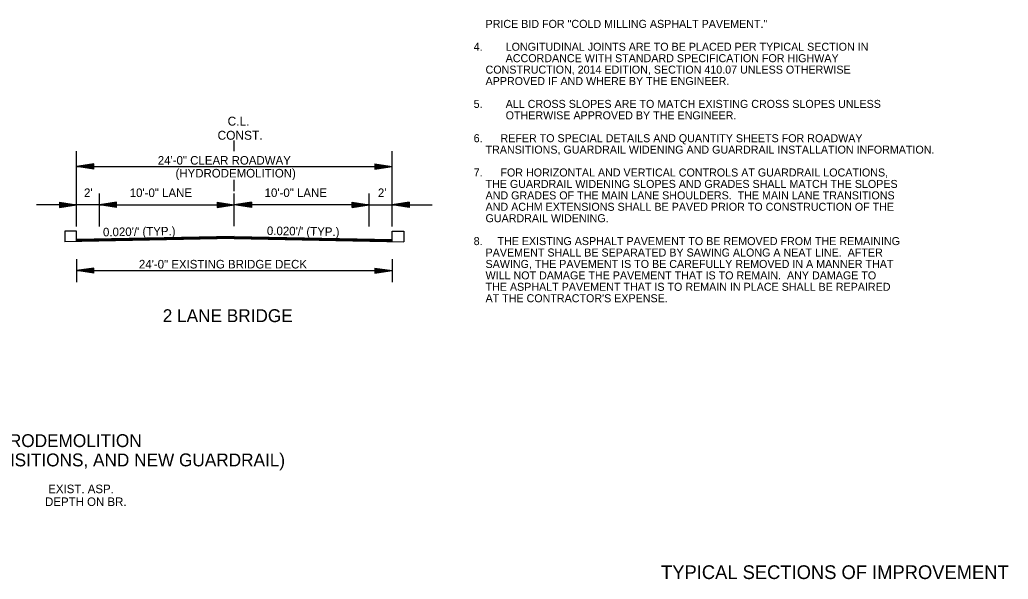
# Model space of a CAD drawing. Extents: x 544259 to 1930787, y -1961343 to 596640.
# Drawn here: x 544903 to 545768, y -1961343 to -1960854 of the extents above; entities that cross this region are included whole.
import ezdxf

# ---------------------------------------------------------------- set-up
doc = ezdxf.new("R2010")
doc.units = 0
for name, color, linetype in [('R_Border', 7, 'Continuous'), ('R_Border Notes', 7, 'Continuous'), ('R_Draft', 7, 'Continuous')]:
    doc.layers.add(name, color=color, linetype=linetype)

msp = doc.modelspace()

# ---------------------------------------------------------------- linework, layer by layer
at = {"layer": 'R_Border'}
for p, q in [((544952.87, -1961015.49), (544917.87, -1961015.49)), ((545228.87, -1961015.49), (545263.87, -1961015.49)), ((544942.71, -1961038.56), (544942.69, -1961047.73)), ((544952.87, -1961038.56), (544942.71, -1961038.56)), ((544952.87, -1961047.36), (544952.87, -1961038.56)), ((545228.87, -1961047.36), (545228.87, -1961038.56)), ((545228.87, -1961038.56), (545239.04, -1961038.56)), ((545239.04, -1961038.56), (545239.05, -1961047.73))]:
    msp.add_line(p, q, dxfattribs=at)
at = {"layer": 'R_Draft'}
for p, q in [((545090.87, -1960968.54), (545090.87, -1960959.24)), ((544952.87, -1961034.32), (544952.87, -1960968.59)), ((545228.87, -1961034.32), (545228.87, -1960968.59)), ((544967.87, -1960979.7), (544952.87, -1960981.95)), ((544967.87, -1960980.08), (544955.38, -1960981.95)), ((544967.87, -1960980.46), (544957.96, -1960981.95)), ((544967.87, -1960980.84), (544960.46, -1960981.95)), ((544967.87, -1960984.2), (544967.87, -1960979.7)), ((545213.87, -1960979.7), (545228.87, -1960981.95)), ((545213.87, -1960979.7), (545213.87, -1960984.2)), ((545213.87, -1960980.08), (545226.37, -1960981.95)), ((545213.87, -1960980.46), (545223.79, -1960981.95)), ((545213.87, -1960980.84), (545221.29, -1960981.95)), ((544952.87, -1960981.95), (545228.87, -1960981.95)), ((544967.87, -1960984.2), (544952.87, -1960981.95)), ((544967.87, -1960983.83), (544955.38, -1960981.95)), ((544967.87, -1960983.45), (544957.96, -1960981.95)), ((544967.87, -1960983.07), (544960.46, -1960981.95)), ((544967.87, -1960981.22), (544963, -1960981.95)), ((544967.87, -1960982.68), (544963, -1960981.95)), ((544967.87, -1960981.6), (544965.5, -1960981.95)), ((544967.87, -1960982.31), (544965.5, -1960981.95)), ((545213.87, -1960981.23), (545218.75, -1960981.95)), ((545213.87, -1960981.6), (545216.24, -1960981.95)), ((545213.87, -1960984.2), (545228.87, -1960981.95)), ((545213.87, -1960982.69), (545218.75, -1960981.95)), ((545213.87, -1960983.45), (545223.79, -1960981.95)), ((545213.87, -1960983.83), (545226.37, -1960981.95)), ((545213.87, -1960983.07), (545221.29, -1960981.95)), ((545213.87, -1960982.31), (545216.24, -1960981.95)), ((545090.87, -1961003.48), (545090.87, -1960993.61)), ((544972.87, -1961034.32), (544972.87, -1961005.6)), ((545090.87, -1961034.15), (545090.87, -1961005.6)), ((545208.87, -1961034.32), (545208.87, -1961005.6)), ((544937.87, -1961013.24), (544952.87, -1961015.49)), ((544937.87, -1961013.24), (544937.87, -1961017.74)), ((544937.87, -1961013.62), (544950.37, -1961015.49)), ((544937.87, -1961014), (544947.79, -1961015.49)), ((544937.87, -1961014.37), (544945.29, -1961015.49)), ((544937.87, -1961014.76), (544942.75, -1961015.49)), ((544937.87, -1961015.14), (544940.24, -1961015.49)), ((544937.87, -1961017.74), (544952.87, -1961015.49)), ((544937.87, -1961016.23), (544942.75, -1961015.49)), ((544937.87, -1961016.98), (544947.79, -1961015.49)), ((544937.87, -1961017.37), (544950.37, -1961015.49)), ((544937.87, -1961016.61), (544945.29, -1961015.49)), ((544937.87, -1961015.84), (544940.24, -1961015.49)), ((544972.87, -1961015.49), (544947.87, -1961015.49)), ((544987.87, -1961013.24), (544972.87, -1961015.49)), ((544987.87, -1961017.74), (544972.87, -1961015.49)), ((544972.87, -1961015.49), (545090.87, -1961015.49)), ((544987.87, -1961013.62), (544975.38, -1961015.49)), ((544987.87, -1961017.37), (544975.38, -1961015.49)), ((544987.87, -1961014), (544977.96, -1961015.49)), ((544987.87, -1961016.98), (544977.96, -1961015.49)), ((544987.87, -1961014.37), (544980.46, -1961015.49)), ((544987.87, -1961016.61), (544980.46, -1961015.49)), ((544987.87, -1961014.76), (544983, -1961015.49)), ((544987.87, -1961016.22), (544983, -1961015.49)), ((544987.87, -1961015.14), (544985.5, -1961015.49)), ((544987.87, -1961015.84), (544985.5, -1961015.49)), ((544987.87, -1961017.74), (544987.87, -1961013.24)), ((545075.87, -1961013.24), (545090.87, -1961015.49)), ((545075.87, -1961013.24), (545075.87, -1961017.74)), ((545075.87, -1961013.62), (545088.37, -1961015.49)), ((545075.87, -1961014), (545085.79, -1961015.49)), ((545075.87, -1961014.37), (545083.29, -1961015.49)), ((545075.87, -1961014.76), (545080.75, -1961015.49)), ((545075.87, -1961015.14), (545078.24, -1961015.49)), ((545075.87, -1961017.74), (545090.87, -1961015.49)), ((545075.87, -1961016.23), (545080.75, -1961015.49)), ((545075.87, -1961016.98), (545085.79, -1961015.49)), ((545075.87, -1961017.37), (545088.37, -1961015.49)), ((545075.87, -1961016.61), (545083.29, -1961015.49)), ((545075.87, -1961015.84), (545078.24, -1961015.49)), ((545105.87, -1961013.24), (545090.87, -1961015.49)), ((545208.87, -1961015.49), (545090.87, -1961015.49)), ((545105.87, -1961017.74), (545090.87, -1961015.49)), ((545105.87, -1961013.62), (545093.38, -1961015.49)), ((545105.87, -1961017.37), (545093.38, -1961015.49)), ((545105.87, -1961014), (545095.96, -1961015.49)), ((545105.87, -1961016.98), (545095.96, -1961015.49)), ((545105.87, -1961014.37), (545098.46, -1961015.49)), ((545105.87, -1961016.61), (545098.46, -1961015.49)), ((545105.87, -1961014.76), (545101, -1961015.49)), ((545105.87, -1961016.23), (545101, -1961015.49)), ((545105.87, -1961015.14), (545103.5, -1961015.49)), ((545105.87, -1961015.84), (545103.5, -1961015.49)), ((545105.87, -1961013.24), (545105.87, -1961017.74)), ((545193.87, -1961013.24), (545208.87, -1961015.49)), ((545193.87, -1961017.74), (545193.87, -1961013.24)), ((545193.87, -1961013.62), (545206.37, -1961015.49)), ((545193.87, -1961014), (545203.79, -1961015.49)), ((545193.87, -1961014.37), (545201.29, -1961015.49)), ((545193.87, -1961014.76), (545198.75, -1961015.49)), ((545193.87, -1961015.14), (545196.24, -1961015.49)), ((545193.87, -1961017.74), (545208.87, -1961015.49)), ((545193.87, -1961016.22), (545198.75, -1961015.49)), ((545193.87, -1961016.98), (545203.79, -1961015.49)), ((545193.87, -1961017.37), (545206.37, -1961015.49)), ((545193.87, -1961016.61), (545201.29, -1961015.49)), ((545193.87, -1961015.84), (545196.24, -1961015.49)), ((545208.87, -1961015.49), (545228.87, -1961015.49)), ((545243.87, -1961013.24), (545228.87, -1961015.49)), ((545243.87, -1961017.74), (545228.87, -1961015.49)), ((545243.87, -1961013.62), (545231.38, -1961015.49)), ((545243.87, -1961017.37), (545231.38, -1961015.49)), ((545243.87, -1961014), (545233.96, -1961015.49)), ((545243.87, -1961016.98), (545233.96, -1961015.49)), ((545243.87, -1961014.37), (545236.46, -1961015.49)), ((545243.87, -1961016.61), (545236.46, -1961015.49)), ((545243.87, -1961014.76), (545239, -1961015.49)), ((545243.87, -1961016.23), (545239, -1961015.49)), ((545243.87, -1961015.14), (545241.5, -1961015.49)), ((545243.87, -1961015.84), (545241.5, -1961015.49)), ((545243.87, -1961013.24), (545243.87, -1961017.74)), ((545090.91, -1961044.77), (544942.69, -1961047.73)), ((545090.87, -1961043.1), (544952.87, -1961045.86)), ((545090.88, -1961043.4), (544952.87, -1961046.16)), ((545090.89, -1961043.7), (544952.87, -1961046.46)), ((545090.89, -1961044), (544952.87, -1961046.76)), ((545090.9, -1961044.3), (544952.87, -1961047.06)), ((545090.9, -1961044.6), (544952.87, -1961047.36)), ((545090.84, -1961044.6), (545228.87, -1961047.36)), ((545090.84, -1961044.77), (545239.05, -1961047.73)), ((545090.85, -1961044.3), (545228.87, -1961047.06)), ((545090.86, -1961043.7), (545228.87, -1961046.46)), ((545090.86, -1961044), (545228.87, -1961046.76)), ((545090.87, -1961043.1), (545228.87, -1961045.86)), ((545090.87, -1961043.4), (545228.87, -1961046.16)), ((544952.87, -1961062.96), (544952.87, -1961082.96)), ((545228.87, -1961062.96), (545228.87, -1961082.96)), ((544967.87, -1961070.71), (544952.87, -1961072.96)), ((544952.87, -1961072.96), (545228.87, -1961072.96)), ((544967.87, -1961075.21), (544952.87, -1961072.96)), ((544967.87, -1961071.08), (544955.38, -1961072.96)), ((544967.87, -1961074.83), (544955.38, -1961072.96)), ((544967.87, -1961071.46), (544957.96, -1961072.96)), ((544967.87, -1961074.45), (544957.96, -1961072.96)), ((544967.87, -1961071.84), (544960.46, -1961072.96)), ((544967.87, -1961074.07), (544960.46, -1961072.96)), ((544967.87, -1961072.22), (544963, -1961072.96)), ((544967.87, -1961073.68), (544963, -1961072.96)), ((544967.87, -1961072.6), (544965.5, -1961072.96)), ((544967.87, -1961073.31), (544965.5, -1961072.96)), ((544967.87, -1961075.21), (544967.87, -1961070.71)), ((545213.87, -1961070.71), (545228.87, -1961072.96)), ((545213.87, -1961070.71), (545213.87, -1961075.21)), ((545213.87, -1961071.08), (545226.37, -1961072.96)), ((545213.87, -1961071.46), (545223.79, -1961072.96)), ((545213.87, -1961071.84), (545221.29, -1961072.96)), ((545213.87, -1961072.23), (545218.75, -1961072.96)), ((545213.87, -1961072.6), (545216.24, -1961072.96)), ((545213.87, -1961075.21), (545228.87, -1961072.96)), ((545213.87, -1961073.69), (545218.75, -1961072.96)), ((545213.87, -1961074.45), (545223.79, -1961072.96)), ((545213.87, -1961074.83), (545226.37, -1961072.96)), ((545213.87, -1961074.07), (545221.29, -1961072.96)), ((545213.87, -1961073.31), (545216.24, -1961072.96))]:
    msp.add_line(p, q, dxfattribs=at)

# ---------------------------------------------------------------- texts
at = {"layer": 'R_Border'}
msp.add_text('TYPICAL SECTIONS OF IMPROVEMENT', height=12, rotation=360, dxfattribs=at).set_placement((545464.19, -1961342.8))
at = {"layer": 'R_Border Notes'}
for s, p in [('    PRICE BID FOR "COLD MILLING ASPHALT PAVEMENT."', (545300.26, -1960860.66)), ('4.', (545300.26, -1960880.66)), ('LONGITUDINAL JOINTS ARE TO BE PLACED PER TYPICAL SECTION IN ', (545328.26, -1960880.66)), ('ACCORDANCE WITH STANDARD SPECIFICATION FOR HIGHWAY', (545328.26, -1960890.66)), ('    CONSTRUCTION, 2014 EDITION, SECTION 410.07 UNLESS OTHERWISE', (545300.26, -1960900.66)), ('    APPROVED IF AND WHERE BY THE ENGINEER.', (545300.26, -1960910.66)), ('5.', (545300.26, -1960930.66)), ('ALL CROSS SLOPES ARE TO MATCH EXISTING CROSS SLOPES UNLESS ', (545328.26, -1960930.66)), ('OTHERWISE APPROVED BY THE ENGINEER.', (545328.26, -1960940.66)), ('6.      REFER TO SPECIAL DETAILS AND QUANTITY SHEETS FOR ROADWAY', (545300.26, -1960960.66)), ('    TRANSITIONS, GUARDRAIL WIDENING AND GUARDRAIL INSTALLATION INFORMATION.', (545300.26, -1960970.66)), ('7.      FOR HORIZONTAL AND VERTICAL CONTROLS AT GUARDRAIL LOCATIONS,', (545300.26, -1960990.66)), ('    THE GUARDRAIL WIDENING SLOPES AND GRADES SHALL MATCH THE SLOPES', (545300.26, -1961000.66)), ('    AND GRADES OF THE MAIN LANE SHOULDERS.  THE MAIN LANE TRANSITIONS', (545300.26, -1961010.66)), ('    AND ACHM EXTENSIONS SHALL BE PAVED PRIOR TO CONSTRUCTION OF THE', (545300.26, -1961020.66)), ('    GUARDRAIL WIDENING.', (545300.26, -1961030.66)), ('8.     THE EXISTING ASPHALT PAVEMENT TO BE REMOVED FROM THE REMAINING', (545300.26, -1961050.66)), ('    PAVEMENT SHALL BE SEPARATED BY SAWING ALONG A NEAT LINE.  AFTER', (545300.26, -1961060.66)), ('    SAWING, THE PAVEMENT IS TO BE CAREFULLY REMOVED IN A MANNER THAT ', (545300.26, -1961070.66)), ('    WILL NOT DAMAGE THE PAVEMENT THAT IS TO REMAIN.  ANY DAMAGE TO', (545300.26, -1961080.66)), ('    THE ASPHALT PAVEMENT THAT IS TO REMAIN IN PLACE SHALL BE REPAIRED', (545300.26, -1961090.66)), ("    AT THE CONTRACTOR'S EXPENSE.", (545300.26, -1961100.66))]:
    msp.add_text(s, height=7, dxfattribs=at).set_placement(p)
at = {"layer": 'R_Draft'}
for s, height, p in [('C.L.', 7.8, (545085.03, -1960946.14)), ('CONST.', 7.8, (545076.24, -1960958.51)), ('24\'-0" CLEAR ROADWAY ', 7.5, (545023.96, -1960980.28)), ('(HYDRODEMOLITION)', 7.5, (545039.44, -1960991.53)), ("2'", 7.5, (544959.41, -1961008.63)), ('10\'-0" LANE', 7.5, (544999.39, -1961008.63)), ('10\'-0" LANE', 7.5, (545117.39, -1961008.63)), ("2'", 7.5, (545216.48, -1961008.63)), ('24\'-0" EXISTING BRIDGE DECK', 7.5, (545007.43, -1961071.12)), ('2 LANE BRIDGE', 11.25, (545028.28, -1961118.03)), ('24 FT. CLEAR ROADWAY BRIDGE - HYDRODEMOLITION', 11.25, (544606.98, -1961227.36)), ('(BRIDGE WITH MILLING ASPHALT ON BR. DECK, ROAD TRANSITIONS, AND NEW GUARDRAIL)', 11.25, (544457.41, -1961244.23)), (' EXIST. ASP. ', 7.5, (544925.34, -1961267.68)), ('DEPTH ON BR. ', 7.5, (544925.34, -1961278.93))]:
    msp.add_text(s, height=height, dxfattribs=at).set_placement(p)
for rotation, p in [(0.87191, (544976.07, -1961043.05)), (359.12809, (545119.36, -1961041.82))]:
    msp.add_text("0.020'/' (TYP.)", height=7.5, rotation=rotation, dxfattribs=at).set_placement(p)

doc.saveas('drawing.dxf')
